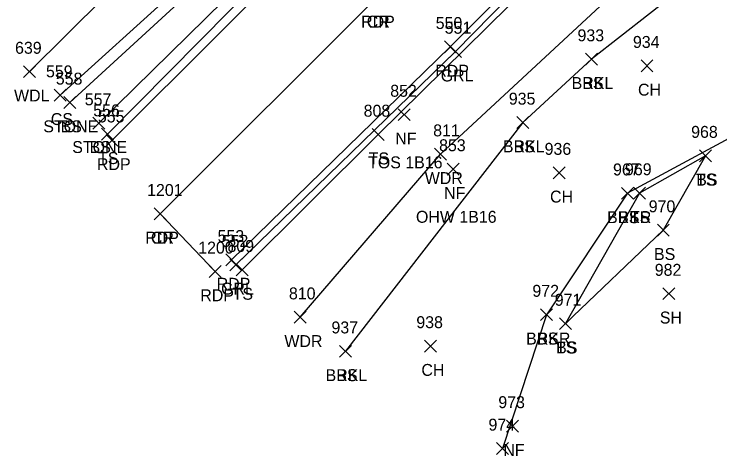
# Model space of a CAD drawing. Extents: x 1528286 to 1556263, y 492387 to 508952.
# Drawn here: x 1528302.6 to 1528421, y 492463.4 to 492537.5 of the extents above; entities that cross this region are included whole.
import ezdxf

# ---------------------------------------------------------------- set-up
doc = ezdxf.new("R2010")
doc.units = 0
for name, color, linetype in [('L_A', 7, 'Continuous'), ('L_C', 7, 'Continuous'), ('L_I', 7, 'Continuous'), ('L_TIC', 7, 'Continuous'), ('LASF', 7, 'Continuous'), ('LAWA', 7, 'Continuous'), ('LAWE', 7, 'Continuous'), ('LELB', 7, 'Continuous'), ('P_A', 7, 'Continuous'), ('P_I', 7, 'Continuous'), ('P_TIC', 7, 'Continuous'), ('PET', 7, 'Continuous'), ('PRC', 7, 'Continuous'), ('R_A', 7, 'Continuous'), ('R_I', 7, 'Continuous'), ('R_TIC', 7, 'Continuous'), ('RGR', 7, 'Continuous')]:
    doc.layers.add(name, color=color, linetype=linetype)

msp = doc.modelspace()

# ---------------------------------------------------------------- linework, layer by layer
at = {"layer": 'L_TIC'}
for points in [[(1528398.48, 492528.93), (1528400.48, 492530.93)], [(1528400.48, 492528.93), (1528398.48, 492530.93)], [(1528398.48, 492528.93), (1528400.48, 492530.93)], [(1528400.48, 492528.93), (1528398.48, 492530.93)], [(1528398.48, 492528.93), (1528400.48, 492530.93)], [(1528400.48, 492528.93), (1528398.48, 492530.93)], [(1528398.48, 492528.93), (1528400.48, 492530.93)], [(1528400.48, 492528.93), (1528398.48, 492530.93)], [(1528407.78, 492527.82), (1528409.78, 492529.82)], [(1528409.78, 492527.82), (1528407.78, 492529.82)], [(1528407.78, 492527.82), (1528409.78, 492529.82)], [(1528409.78, 492527.82), (1528407.78, 492529.82)], [(1528304.14, 492526.84), (1528306.14, 492528.84)], [(1528306.14, 492526.84), (1528304.14, 492528.84)], [(1528304.14, 492526.84), (1528306.14, 492528.84)], [(1528306.14, 492526.84), (1528304.14, 492528.84)], [(1528309.29, 492522.89), (1528311.29, 492524.89)], [(1528311.29, 492522.89), (1528309.29, 492524.89)], [(1528309.29, 492522.89), (1528311.29, 492524.89)], [(1528311.29, 492522.89), (1528309.29, 492524.89)], [(1528310.93, 492521.67), (1528312.93, 492523.67)], [(1528312.93, 492521.67), (1528310.93, 492523.67)], [(1528310.93, 492521.67), (1528312.93, 492523.67)], [(1528312.93, 492521.67), (1528310.93, 492523.67)], [(1528310.93, 492521.67), (1528312.93, 492523.67)], [(1528312.93, 492521.67), (1528310.93, 492523.67)], [(1528310.93, 492521.67), (1528312.93, 492523.67)], [(1528312.93, 492521.67), (1528310.93, 492523.67)], [(1528367.05, 492519.63), (1528369.05, 492521.63)], [(1528369.05, 492519.63), (1528367.05, 492521.63)], [(1528367.05, 492519.63), (1528369.05, 492521.63)], [(1528369.05, 492519.63), (1528367.05, 492521.63)], [(1528315.79, 492518.2), (1528317.79, 492520.2)], [(1528317.79, 492518.2), (1528315.79, 492520.2)], [(1528315.79, 492518.2), (1528317.79, 492520.2)], [(1528317.79, 492518.2), (1528315.79, 492520.2)], [(1528315.79, 492518.2), (1528317.79, 492520.2)], [(1528317.79, 492518.2), (1528315.79, 492520.2)], [(1528315.79, 492518.2), (1528317.79, 492520.2)], [(1528317.79, 492518.2), (1528315.79, 492520.2)], [(1528386.95, 492518.31), (1528388.95, 492520.31)], [(1528388.95, 492518.31), (1528386.95, 492520.31)], [(1528386.95, 492518.31), (1528388.95, 492520.31)], [(1528388.95, 492518.31), (1528386.95, 492520.31)], [(1528386.95, 492518.31), (1528388.95, 492520.31)], [(1528388.95, 492518.31), (1528386.95, 492520.31)], [(1528386.95, 492518.31), (1528388.95, 492520.31)], [(1528388.95, 492518.31), (1528386.95, 492520.31)], [(1528317.25, 492516.35), (1528319.25, 492518.35)], [(1528319.25, 492516.35), (1528317.25, 492518.35)], [(1528317.25, 492516.35), (1528319.25, 492518.35)], [(1528319.25, 492516.35), (1528317.25, 492518.35)], [(1528362.67, 492516.29), (1528364.67, 492518.29)], [(1528364.67, 492516.29), (1528362.67, 492518.29)], [(1528362.67, 492516.29), (1528364.67, 492518.29)], [(1528364.67, 492516.29), (1528362.67, 492518.29)], [(1528373.13, 492512.99), (1528375.13, 492514.99)], [(1528375.13, 492512.99), (1528373.13, 492514.99)], [(1528373.13, 492512.99), (1528375.13, 492514.99)], [(1528375.13, 492512.99), (1528373.13, 492514.99)], [(1528417.6, 492512.74), (1528419.6, 492514.74)], [(1528419.6, 492512.74), (1528417.6, 492514.74)], [(1528417.6, 492512.74), (1528419.6, 492514.74)], [(1528419.6, 492512.74), (1528417.6, 492514.74)], [(1528417.6, 492512.74), (1528419.6, 492514.74)], [(1528419.6, 492512.74), (1528417.6, 492514.74)], [(1528417.6, 492512.74), (1528419.6, 492514.74)], [(1528419.6, 492512.74), (1528417.6, 492514.74)], [(1528375.26, 492510.5), (1528377.26, 492512.5)], [(1528377.26, 492510.5), (1528375.26, 492512.5)], [(1528375.26, 492510.5), (1528377.26, 492512.5)], [(1528377.26, 492510.5), (1528375.26, 492512.5)], [(1528393.02, 492509.89), (1528395.02, 492511.89)], [(1528395.02, 492509.89), (1528393.02, 492511.89)], [(1528393.02, 492509.89), (1528395.02, 492511.89)], [(1528395.02, 492509.89), (1528393.02, 492511.89)], [(1528404.49, 492506.44), (1528406.49, 492508.44)], [(1528406.49, 492506.44), (1528404.49, 492508.44)], [(1528404.49, 492506.44), (1528406.49, 492508.44)], [(1528406.49, 492506.44), (1528404.49, 492508.44)], [(1528404.49, 492506.44), (1528406.49, 492508.44)], [(1528406.49, 492506.44), (1528404.49, 492508.44)], [(1528404.49, 492506.44), (1528406.49, 492508.44)], [(1528406.49, 492506.44), (1528404.49, 492508.44)], [(1528406.51, 492506.47), (1528408.51, 492508.47)], [(1528408.51, 492506.47), (1528406.51, 492508.47)], [(1528406.51, 492506.47), (1528408.51, 492508.47)], [(1528408.51, 492506.47), (1528406.51, 492508.47)], [(1528410.52, 492500.26), (1528412.52, 492502.26)], [(1528412.52, 492500.26), (1528410.52, 492502.26)], [(1528410.52, 492500.26), (1528412.52, 492502.26)], [(1528412.52, 492500.26), (1528410.52, 492502.26)], [(1528339.83, 492493.6), (1528341.83, 492495.6)], [(1528341.83, 492493.6), (1528339.83, 492495.6)], [(1528339.83, 492493.6), (1528341.83, 492495.6)], [(1528341.83, 492493.6), (1528339.83, 492495.6)], [(1528411.44, 492489.61), (1528413.44, 492491.61)], [(1528413.44, 492489.61), (1528411.44, 492491.61)], [(1528411.44, 492489.61), (1528413.44, 492491.61)], [(1528413.44, 492489.61), (1528411.44, 492491.61)], [(1528390.91, 492486.09), (1528392.91, 492488.09)], [(1528392.91, 492486.09), (1528390.91, 492488.09)], [(1528390.91, 492486.09), (1528392.91, 492488.09)], [(1528392.91, 492486.09), (1528390.91, 492488.09)], [(1528390.91, 492486.09), (1528392.91, 492488.09)], [(1528392.91, 492486.09), (1528390.91, 492488.09)], [(1528390.91, 492486.09), (1528392.91, 492488.09)], [(1528392.91, 492486.09), (1528390.91, 492488.09)], [(1528349.57, 492485.66), (1528351.57, 492487.66)], [(1528351.57, 492485.66), (1528349.57, 492487.66)], [(1528349.57, 492485.66), (1528351.57, 492487.66)], [(1528351.57, 492485.66), (1528349.57, 492487.66)], [(1528394.09, 492484.59), (1528396.09, 492486.59)], [(1528396.09, 492484.59), (1528394.09, 492486.59)], [(1528394.09, 492484.59), (1528396.09, 492486.59)], [(1528396.09, 492484.59), (1528394.09, 492486.59)], [(1528394.09, 492484.59), (1528396.09, 492486.59)], [(1528396.09, 492484.59), (1528394.09, 492486.59)], [(1528394.09, 492484.59), (1528396.09, 492486.59)], [(1528396.09, 492484.59), (1528394.09, 492486.59)], [(1528371.44, 492480.83), (1528373.44, 492482.83)], [(1528373.44, 492480.83), (1528371.44, 492482.83)], [(1528371.44, 492480.83), (1528373.44, 492482.83)], [(1528373.44, 492480.83), (1528371.44, 492482.83)], [(1528357.2, 492479.95), (1528359.2, 492481.95)], [(1528359.2, 492479.95), (1528357.2, 492481.95)], [(1528357.2, 492479.95), (1528359.2, 492481.95)], [(1528359.2, 492479.95), (1528357.2, 492481.95)], [(1528357.2, 492479.95), (1528359.2, 492481.95)], [(1528359.2, 492479.95), (1528357.2, 492481.95)], [(1528357.2, 492479.95), (1528359.2, 492481.95)], [(1528359.2, 492479.95), (1528357.2, 492481.95)], [(1528385.19, 492467.42), (1528387.19, 492469.42)], [(1528387.19, 492467.42), (1528385.19, 492469.42)], [(1528385.19, 492467.42), (1528387.19, 492469.42)], [(1528387.19, 492467.42), (1528385.19, 492469.42)], [(1528383.54, 492463.65), (1528385.54, 492465.65)], [(1528385.54, 492463.65), (1528383.54, 492465.65)], [(1528383.54, 492463.65), (1528385.54, 492465.65)], [(1528385.54, 492463.65), (1528383.54, 492465.65)], [(1528383.54, 492463.65), (1528385.54, 492465.65)], [(1528385.54, 492463.65), (1528383.54, 492465.65)], [(1528383.54, 492463.65), (1528385.54, 492465.65)], [(1528385.54, 492463.65), (1528383.54, 492465.65)]]:
    msp.add_lwpolyline(points, dxfattribs=at)
at = {"layer": 'LASF'}
for points in [[(1528311.93, 492522.67), (1528350.13, 492557.71), (1528387.18, 492594.6), (1528424, 492629.25), (1528451.68, 492657.61), (1528445.37, 492665.36)], [(1528311.93, 492522.67), (1528350.13, 492557.71), (1528387.18, 492594.6), (1528424, 492629.25), (1528451.68, 492657.61), (1528445.37, 492665.36)], [(1528316.79, 492519.2), (1528352.68, 492554.48), (1528389.42, 492592.22), (1528426.31, 492626.76), (1528455.19, 492654.8), (1528460.13, 492658.52), (1528463.91, 492659.12), (1528453.91, 492663.5)], [(1528316.79, 492519.2), (1528352.68, 492554.48), (1528389.42, 492592.22), (1528426.31, 492626.76), (1528455.19, 492654.8), (1528460.13, 492658.52), (1528463.91, 492659.12), (1528453.91, 492663.5)]]:
    msp.add_lwpolyline(points, dxfattribs=at)
at = {"layer": 'LAWA'}
for points in [[(1528305.14, 492527.84), (1528342.93, 492565.34), (1528378.69, 492601.44), (1528416.01, 492639), (1528453.01, 492673.15), (1528472.8, 492690.43), (1528460.27, 492718.44)], [(1528305.14, 492527.84), (1528342.93, 492565.34), (1528378.69, 492601.44), (1528416.01, 492639), (1528453.01, 492673.15), (1528472.8, 492690.43), (1528460.27, 492718.44)], [(1528350.57, 492486.66), (1528374.13, 492513.99), (1528413.92, 492550.92), (1528435.09, 492569.85), (1528453.54, 492583.2), (1528487.05, 492613.16), (1528503.18, 492626.81), (1528522.58, 492648.48), (1528559.07, 492677.55), (1528579.27, 492695.13), (1528598.45, 492712.96), (1528609.01, 492715.03)], [(1528350.57, 492486.66), (1528374.13, 492513.99), (1528413.92, 492550.92), (1528435.09, 492569.85), (1528453.54, 492583.2), (1528487.05, 492613.16), (1528503.18, 492626.81), (1528522.58, 492648.48), (1528559.07, 492677.55), (1528579.27, 492695.13), (1528598.45, 492712.96), (1528609.01, 492715.03)]]:
    msp.add_lwpolyline(points, dxfattribs=at)
at = {"layer": 'LAWE'}
for points in [[(1528639.89, 492735.15), (1528628.64, 492716.2), (1528619.32, 492697.77), (1528600.01, 492685.78), (1528586.49, 492675.21), (1528555.76, 492651.71), (1528552.06, 492644.14), (1528537.63, 492632.53), (1528523.34, 492621.85), (1528510.87, 492609.53), (1528497.29, 492599.49), (1528482.78, 492583.15), (1528460.77, 492562.05), (1528436.99, 492551.7), (1528418.95, 492545.2), (1528399.48, 492529.93), (1528387.95, 492519.31), (1528358.2, 492480.95)], [(1528639.89, 492735.15), (1528628.64, 492716.2), (1528619.32, 492697.77), (1528600.01, 492685.78), (1528586.49, 492675.21), (1528555.76, 492651.71), (1528552.06, 492644.14), (1528537.63, 492632.53), (1528523.34, 492621.85), (1528510.87, 492609.53), (1528497.29, 492599.49), (1528482.78, 492583.15), (1528460.77, 492562.05), (1528436.99, 492551.7), (1528418.95, 492545.2), (1528399.48, 492529.93), (1528387.95, 492519.31), (1528358.2, 492480.95)], [(1528645.44, 492730.64), (1528651.62, 492718.64), (1528645.74, 492704.77), (1528631.81, 492684.8), (1528615.48, 492671.09), (1528597.13, 492648.32), (1528570.32, 492633.93), (1528549.93, 492614.14), (1528527.11, 492580.82), (1528486.91, 492550.69), (1528466.24, 492548.44), (1528453.39, 492536.12), (1528428.92, 492520.07), (1528405.49, 492507.44), (1528391.91, 492487.09), (1528384.54, 492464.65)], [(1528645.44, 492730.64), (1528651.62, 492718.64), (1528645.74, 492704.77), (1528631.81, 492684.8), (1528615.48, 492671.09), (1528597.13, 492648.32), (1528570.32, 492633.93), (1528549.93, 492614.14), (1528527.11, 492580.82), (1528486.91, 492550.69), (1528466.24, 492548.44), (1528453.39, 492536.12), (1528428.92, 492520.07), (1528405.49, 492507.44), (1528391.91, 492487.09), (1528384.54, 492464.65)]]:
    msp.add_lwpolyline(points, dxfattribs=at)
at = {"layer": 'LELB'}
for points in [[(1528627.54, 492747.2), (1528602.25, 492728.24), (1528590.92, 492720.18), (1528561.7, 492697.24), (1528528.44, 492669.89), (1528504.89, 492649.18), (1528486.55, 492633.13), (1528477.15, 492624.6), (1528462.19, 492611.3), (1528435.47, 492586.89), (1528420.5, 492573.08), (1528389.26, 492542.58), (1528363.67, 492517.29), (1528340.83, 492494.6)], [(1528627.54, 492747.2), (1528602.25, 492728.24), (1528590.92, 492720.18), (1528561.7, 492697.24), (1528528.44, 492669.89), (1528504.89, 492649.18), (1528486.55, 492633.13), (1528477.15, 492624.6), (1528462.19, 492611.3), (1528435.47, 492586.89), (1528420.5, 492573.08), (1528389.26, 492542.58), (1528363.67, 492517.29), (1528340.83, 492494.6)], [(1528619.63, 492709.3), (1528607.89, 492695.26), (1528600.01, 492685.78), (1528586.49, 492675.21), (1528555.76, 492651.71), (1528552.06, 492644.14), (1528537.63, 492632.53), (1528523.34, 492621.85), (1528510.87, 492609.53), (1528497.29, 492599.49), (1528482.78, 492583.15), (1528460.77, 492562.05), (1528436.99, 492551.7), (1528418.95, 492545.2), (1528399.48, 492529.93), (1528387.95, 492519.31), (1528358.2, 492480.95)], [(1528619.63, 492709.3), (1528607.89, 492695.26), (1528600.01, 492685.78), (1528586.49, 492675.21), (1528555.76, 492651.71), (1528552.06, 492644.14), (1528537.63, 492632.53), (1528523.34, 492621.85), (1528510.87, 492609.53), (1528497.29, 492599.49), (1528482.78, 492583.15), (1528460.77, 492562.05), (1528436.99, 492551.7), (1528418.95, 492545.2), (1528399.48, 492529.93), (1528387.95, 492519.31), (1528358.2, 492480.95)], [(1528318.25, 492517.35), (1528354.27, 492553.82), (1528390.84, 492589.85), (1528428.18, 492625.46), (1528458.02, 492652.61), (1528463.91, 492659.12), (1528457.38, 492666.33)], [(1528318.25, 492517.35), (1528354.27, 492553.82), (1528390.84, 492589.85), (1528428.18, 492625.46), (1528458.02, 492652.61), (1528463.91, 492659.12), (1528457.38, 492666.33)], [(1528311.93, 492522.67), (1528350.13, 492557.71), (1528387.18, 492594.6), (1528424, 492629.25), (1528451.68, 492657.61), (1528445.37, 492665.36)], [(1528311.93, 492522.67), (1528350.13, 492557.71), (1528387.18, 492594.6), (1528424, 492629.25), (1528451.68, 492657.61), (1528445.37, 492665.36)], [(1528310.29, 492523.89), (1528348.88, 492558.85), (1528386.25, 492595.69), (1528422.77, 492630.31), (1528448.92, 492658.21)], [(1528310.29, 492523.89), (1528348.88, 492558.85), (1528386.25, 492595.69), (1528422.77, 492630.31), (1528448.92, 492658.21)], [(1528316.79, 492519.2), (1528352.68, 492554.48), (1528389.42, 492592.22), (1528426.31, 492626.76), (1528455.19, 492654.8), (1528460.13, 492658.52)], [(1528316.79, 492519.2), (1528352.68, 492554.48), (1528389.42, 492592.22), (1528426.31, 492626.76), (1528455.19, 492654.8), (1528460.13, 492658.52)], [(1528450.79, 492524.49), (1528428.92, 492520.07), (1528405.49, 492507.44), (1528391.91, 492487.09), (1528384.54, 492464.65)], [(1528450.79, 492524.49), (1528428.92, 492520.07), (1528405.49, 492507.44), (1528391.91, 492487.09), (1528384.54, 492464.65)], [(1528418.6, 492513.74), (1528407.51, 492507.47), (1528395.09, 492485.59)], [(1528418.6, 492513.74), (1528411.52, 492501.26), (1528395.09, 492485.59)], [(1528418.6, 492513.74), (1528407.51, 492507.47), (1528395.09, 492485.59)], [(1528418.6, 492513.74), (1528411.52, 492501.26), (1528395.09, 492485.59)]]:
    msp.add_lwpolyline(points, dxfattribs=at)
at = {"layer": 'P_TIC'}
for points in [[(1528374.77, 492530.99), (1528376.77, 492532.99)], [(1528376.77, 492530.99), (1528374.77, 492532.99)], [(1528374.77, 492530.99), (1528376.77, 492532.99)], [(1528376.77, 492530.99), (1528374.77, 492532.99)], [(1528318, 492515.33), (1528320, 492517.33)], [(1528320, 492515.33), (1528318, 492517.33)], [(1528318, 492515.33), (1528320, 492517.33)], [(1528320, 492515.33), (1528318, 492517.33)], [(1528326.09, 492503), (1528328.09, 492505)], [(1528328.09, 492503), (1528326.09, 492505)], [(1528326.09, 492503), (1528328.09, 492505)], [(1528328.09, 492503), (1528326.09, 492505)], [(1528326.09, 492503), (1528328.09, 492505)], [(1528328.09, 492503), (1528326.09, 492505)], [(1528326.09, 492503), (1528328.09, 492505)], [(1528328.09, 492503), (1528326.09, 492505)], [(1528338.08, 492495.27), (1528340.08, 492497.27)], [(1528340.08, 492495.27), (1528338.08, 492497.27)], [(1528338.08, 492495.27), (1528340.08, 492497.27)], [(1528340.08, 492495.27), (1528338.08, 492497.27)], [(1528335.33, 492493.34), (1528337.33, 492495.34)], [(1528337.33, 492493.34), (1528335.33, 492495.34)], [(1528335.33, 492493.34), (1528337.33, 492495.34)], [(1528337.33, 492493.34), (1528335.33, 492495.34)]]:
    msp.add_lwpolyline(points, dxfattribs=at)
at = {"layer": 'PET'}
for points in [[(1528560.52, 492699.26), (1528557.47, 492699.12), (1528553.46, 492694.77), (1528549.1, 492692.72), (1528547.05, 492688.29), (1528537.76, 492682.52), (1528535.94, 492680.25), (1528535.91, 492679.06), (1528519.42, 492665.12), (1528485.65, 492635.11), (1528449.9, 492603.32), (1528443.29, 492597.22), (1528441.44, 492597.06), (1528433.94, 492590.58), (1528430.62, 492585.99), (1528412.09, 492568.52), (1528375.77, 492531.99), (1528339.08, 492496.27)], [(1528560.52, 492699.26), (1528557.47, 492699.12), (1528553.46, 492694.77), (1528549.1, 492692.72), (1528547.05, 492688.29), (1528537.76, 492682.52), (1528535.94, 492680.25), (1528535.91, 492679.06), (1528519.42, 492665.12), (1528485.65, 492635.11), (1528449.9, 492603.32), (1528443.29, 492597.22), (1528441.44, 492597.06), (1528433.94, 492590.58), (1528430.62, 492585.99), (1528412.09, 492568.52), (1528375.77, 492531.99), (1528339.08, 492496.27)], [(1528466.46, 492657.17), (1528429.38, 492624.13), (1528391.88, 492588.94), (1528355.42, 492552.7), (1528319, 492516.33)], [(1528466.46, 492657.17), (1528429.38, 492624.13), (1528391.88, 492588.94), (1528355.42, 492552.7), (1528319, 492516.33)], [(1528336.33, 492494.34), (1528327.09, 492504), (1528363.32, 492540.23), (1528402.17, 492578.12), (1528411.75, 492568.76)], [(1528336.33, 492494.34), (1528327.09, 492504), (1528363.32, 492540.23), (1528402.17, 492578.12), (1528411.75, 492568.76)]]:
    msp.add_lwpolyline(points, dxfattribs=at)
at = {"layer": 'PRC'}
msp.add_lwpolyline([(1528327.09, 492504), (1528363.32, 492540.23), (1528402.17, 492578.12)], dxfattribs=at)
msp.add_lwpolyline([(1528327.09, 492504), (1528363.32, 492540.23), (1528402.17, 492578.12)], dxfattribs=at)
at = {"layer": 'R_TIC'}
for points in [[(1528375.63, 492530.2), (1528377.63, 492532.2)], [(1528377.63, 492530.2), (1528375.63, 492532.2)], [(1528375.63, 492530.2), (1528377.63, 492532.2)], [(1528377.63, 492530.2), (1528375.63, 492532.2)], [(1528338.77, 492494.46), (1528340.77, 492496.46)], [(1528340.77, 492494.46), (1528338.77, 492496.46)], [(1528338.77, 492494.46), (1528340.77, 492496.46)], [(1528340.77, 492494.46), (1528338.77, 492496.46)]]:
    msp.add_lwpolyline(points, dxfattribs=at)
at = {"layer": 'RGR'}
msp.add_lwpolyline([(1528631.56, 492751.52), (1528593.23, 492723.7), (1528555.25, 492694.17), (1528520.29, 492664.56), (1528486.05, 492634.68), (1528450.28, 492602.92), (1528412.92, 492568.15), (1528376.63, 492531.2), (1528339.77, 492495.46)], dxfattribs=at)
msp.add_lwpolyline([(1528631.56, 492751.52), (1528593.23, 492723.7), (1528555.25, 492694.17), (1528520.29, 492664.56), (1528486.05, 492634.68), (1528450.28, 492602.92), (1528412.92, 492568.15), (1528376.63, 492531.2), (1528339.77, 492495.46)], dxfattribs=at)

# ---------------------------------------------------------------- texts
at = {"layer": 'L_A'}
for s, p in [('BRKL', (1528396.13, 492524.93)), ('BRKL', (1528396.13, 492524.93)), ('BS', (1528397.92, 492524.93)), ('BS', (1528397.92, 492524.93)), ('WDL', (1528302.56, 492522.84)), ('WDL', (1528302.56, 492522.84)), ('CH', (1528407.27, 492523.82)), ('CH', (1528407.27, 492523.82)), ('CS', (1528308.73, 492518.89)), ('CS', (1528308.73, 492518.89)), ('STONE', (1528307.47, 492517.67)), ('STONE', (1528307.47, 492517.67)), ('BS', (1528310.37, 492517.67)), ('BS', (1528310.37, 492517.67)), ('NF', (1528366.53, 492515.63)), ('NF', (1528366.53, 492515.63)), ('STONE', (1528312.33, 492514.2)), ('STONE', (1528312.33, 492514.2)), ('BS', (1528315.23, 492514.2)), ('BS', (1528315.23, 492514.2)), ('BRKL', (1528384.6, 492514.31)), ('BRKL', (1528384.6, 492514.31)), ('BS', (1528386.39, 492514.31)), ('BS', (1528386.39, 492514.31)), ('TS', (1528316.66, 492512.35)), ('TS', (1528316.66, 492512.35)), ('TS', (1528362.08, 492512.29)), ('TS', (1528362.08, 492512.29)), ('WDR', (1528371.49, 492508.99)), ('WDR', (1528371.49, 492508.99)), ('TS', (1528417.01, 492508.74)), ('TS', (1528417.01, 492508.74)), ('BS', (1528417.04, 492508.74)), ('BS', (1528417.04, 492508.74)), ('NF', (1528374.74, 492506.5)), ('NF', (1528374.74, 492506.5)), ('CH', (1528392.51, 492505.89)), ('CH', (1528392.51, 492505.89)), ('BRKR', (1528402.08, 492502.44)), ('BRKR', (1528402.08, 492502.44)), ('BS', (1528403.93, 492502.44)), ('BS', (1528403.93, 492502.44)), ('TS', (1528405.92, 492502.47)), ('TS', (1528405.92, 492502.47)), ('BS', (1528409.96, 492496.26)), ('BS', (1528409.96, 492496.26)), ('TS', (1528339.24, 492489.6)), ('TS', (1528339.24, 492489.6)), ('SH', (1528410.93, 492485.61)), ('SH', (1528410.93, 492485.61)), ('WDR', (1528347.93, 492481.66)), ('WDR', (1528347.93, 492481.66)), ('BRKR', (1528388.5, 492482.09)), ('BRKR', (1528388.5, 492482.09)), ('BS', (1528390.35, 492482.09)), ('BS', (1528390.35, 492482.09)), ('TS', (1528393.5, 492480.59)), ('TS', (1528393.5, 492480.59)), ('BS', (1528393.53, 492480.59)), ('BS', (1528393.53, 492480.59)), ('CH', (1528370.92, 492476.83)), ('CH', (1528370.92, 492476.83)), ('BRKL', (1528354.84, 492475.95)), ('BRKL', (1528354.84, 492475.95)), ('BS', (1528356.64, 492475.95)), ('BS', (1528356.64, 492475.95)), ('NF', (1528384.67, 492463.42)), ('NF', (1528384.67, 492463.42))]:
    msp.add_text(s, height=2, dxfattribs=at).set_placement(p)
at = {"layer": 'L_C'}
for s, p in [('TOS 1B16', (1528361.98, 492511.63)), ('TOS 1B16', (1528361.98, 492511.63)), ('OHW 1B16', (1528370.01, 492502.5)), ('OHW 1B16', (1528370.01, 492502.5))]:
    msp.add_text(s, height=2, dxfattribs=at).set_placement(p)
at = {"layer": 'L_I'}
for s, p in [('933', (1528397.12, 492532.93)), ('933', (1528397.12, 492532.93)), ('933', (1528397.12, 492532.93)), ('933', (1528397.12, 492532.93)), ('934', (1528406.42, 492531.82)), ('934', (1528406.42, 492531.82)), ('639', (1528302.73, 492530.84)), ('639', (1528302.73, 492530.84)), ('559', (1528307.92, 492526.89)), ('559', (1528307.92, 492526.89)), ('558', (1528309.57, 492525.67)), ('558', (1528309.57, 492525.67)), ('558', (1528309.57, 492525.67)), ('558', (1528309.57, 492525.67)), ('852', (1528365.69, 492523.63)), ('852', (1528365.69, 492523.63)), ('557', (1528314.43, 492522.2)), ('557', (1528314.43, 492522.2)), ('557', (1528314.43, 492522.2)), ('557', (1528314.43, 492522.2)), ('935', (1528385.59, 492522.31)), ('935', (1528385.59, 492522.31)), ('935', (1528385.59, 492522.31)), ('935', (1528385.59, 492522.31)), ('556', (1528315.84, 492520.35)), ('556', (1528315.84, 492520.35)), ('808', (1528361.23, 492520.29)), ('808', (1528361.23, 492520.29)), ('811', (1528372.9, 492516.99)), ('811', (1528372.9, 492516.99)), ('968', (1528416.19, 492516.74)), ('968', (1528416.19, 492516.74)), ('968', (1528416.19, 492516.74)), ('968', (1528416.19, 492516.74)), ('853', (1528373.89, 492514.5)), ('853', (1528373.89, 492514.5)), ('936', (1528391.6, 492513.89)), ('936', (1528391.6, 492513.89)), ('967', (1528403.08, 492510.44)), ('967', (1528403.08, 492510.44)), ('967', (1528403.08, 492510.44)), ('967', (1528403.08, 492510.44)), ('969', (1528405.09, 492510.47)), ('969', (1528405.09, 492510.47)), ('970', (1528409.07, 492504.26)), ('970', (1528409.07, 492504.26)), ('809', (1528338.38, 492497.6)), ('809', (1528338.38, 492497.6)), ('982', (1528410.08, 492493.61)), ('982', (1528410.08, 492493.61)), ('810', (1528348.69, 492489.66)), ('810', (1528348.69, 492489.66)), ('972', (1528389.55, 492490.09)), ('972', (1528389.55, 492490.09)), ('972', (1528389.55, 492490.09)), ('972', (1528389.55, 492490.09)), ('971', (1528393.3, 492488.59)), ('971', (1528393.3, 492488.59)), ('971', (1528393.3, 492488.59)), ('971', (1528393.3, 492488.59)), ('937', (1528355.83, 492483.95)), ('937', (1528355.83, 492483.95)), ('937', (1528355.83, 492483.95)), ('937', (1528355.83, 492483.95)), ('938', (1528370.07, 492484.83)), ('938', (1528370.07, 492484.83)), ('973', (1528383.83, 492471.42)), ('973', (1528383.83, 492471.42)), ('974', (1528382.18, 492467.65)), ('974', (1528382.18, 492467.65)), ('974', (1528382.18, 492467.65)), ('974', (1528382.18, 492467.65))]:
    msp.add_text(s, height=2, dxfattribs=at).set_placement(p)
at = {"layer": 'P_A'}
for s, p in [('RDP', (1528360.81, 492535.23)), ('RDP', (1528360.81, 492535.23)), ('CR', (1528361.75, 492535.23)), ('CR', (1528361.75, 492535.23)), ('RDP', (1528373.26, 492526.99)), ('RDP', (1528373.26, 492526.99)), ('RDP', (1528316.48, 492511.33)), ('RDP', (1528316.48, 492511.33)), ('RDP', (1528324.58, 492499)), ('RDP', (1528324.58, 492499)), ('CR', (1528325.53, 492499)), ('CR', (1528325.53, 492499)), ('RDP', (1528336.57, 492491.27)), ('RDP', (1528336.57, 492491.27)), ('RDP', (1528333.82, 492489.34)), ('RDP', (1528333.82, 492489.34))]:
    msp.add_text(s, height=2, dxfattribs=at).set_placement(p)
at = {"layer": 'P_I'}
for s, p in [('550', (1528373.32, 492534.99)), ('550', (1528373.32, 492534.99)), ('555', (1528316.63, 492519.33)), ('555', (1528316.63, 492519.33)), ('1201', (1528324.89, 492507)), ('1201', (1528324.89, 492507)), ('1201', (1528324.89, 492507)), ('1201', (1528324.89, 492507)), ('553', (1528336.72, 492499.27)), ('553', (1528336.72, 492499.27)), ('1200', (1528333.47, 492497.34)), ('1200', (1528333.47, 492497.34))]:
    msp.add_text(s, height=2, dxfattribs=at).set_placement(p)
at = {"layer": 'R_A'}
for p in [(1528374.17, 492526.2), (1528374.17, 492526.2), (1528337.31, 492490.46), (1528337.31, 492490.46)]:
    msp.add_text('GRL', height=2, dxfattribs=at).set_placement(p)
at = {"layer": 'R_I'}
for s, p in [('551', (1528374.83, 492534.2)), ('551', (1528374.83, 492534.2)), ('552', (1528337.41, 492498.46)), ('552', (1528337.41, 492498.46))]:
    msp.add_text(s, height=2, dxfattribs=at).set_placement(p)

doc.saveas('drawing.dxf')
